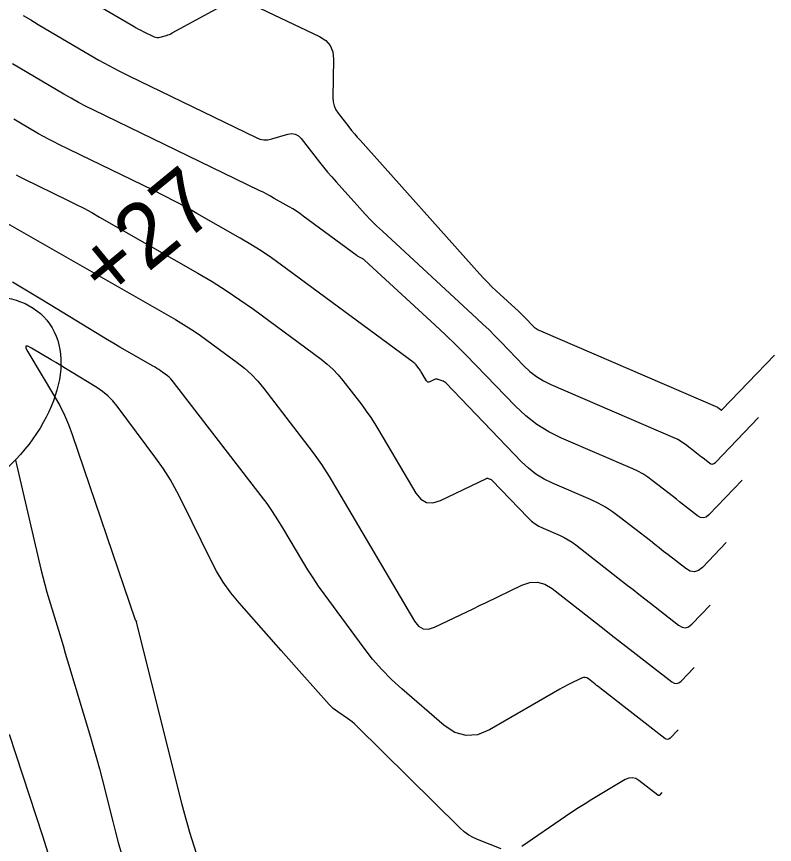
# Model space of a CAD drawing. Extents: x 1005228 to 1008882, y 1883389 to 1885754.
# Drawn here: x 1008264.2 to 1008338, y 1884272.3 to 1884352.9 of the extents above; entities that cross this region are included whole.
import ezdxf

# ---------------------------------------------------------------- set-up
doc = ezdxf.new("R2010")
doc.units = 0
for name, color, linetype in [('C-ANNO-NOTE', 7, 'Continuous'), ('R_Erosion', 7, 'Continuous'), ('S_BASELINE', 7, 'Continuous'), ('S_BRIDGE', 7, 'Continuous')]:
    doc.layers.add(name, color=color, linetype=linetype)

msp = doc.modelspace()

# ---------------------------------------------------------------- linework, layer by layer
at = {"layer": 'C-ANNO-NOTE'}
for points in [[(1008267.118, 1884356.928), (1008275.658, 1884351.886), (1008275.875, 1884351.761), (1008276.094, 1884351.641), (1008276.316, 1884351.525), (1008276.54, 1884351.413), (1008277.608, 1884350.895), (1008277.751, 1884350.84), (1008277.897, 1884350.813), (1008278.045, 1884350.815), (1008278.195, 1884350.844), (1008278.801, 1884351.019), (1008278.951, 1884351.067), (1008279.098, 1884351.122), (1008279.241, 1884351.186), (1008279.381, 1884351.258), (1008284.023, 1884353.818)], [(1008287.355, 1884353.92), (1008293.708, 1884350.909), (1008294.314, 1884350.526), (1008294.743, 1884350.033), (1008294.996, 1884349.43), (1008295.072, 1884348.718), (1008295.016, 1884344.963), (1008295.044, 1884344.55), (1008295.138, 1884344.16), (1008295.299, 1884343.793), (1008295.526, 1884343.448), (1008296.571, 1884342.113), (1008296.835, 1884341.782), (1008297.104, 1884341.455), (1008297.379, 1884341.132), (1008297.659, 1884340.814), (1008309.294, 1884327.798), (1008309.682, 1884327.374), (1008310.08, 1884326.96), (1008310.487, 1884326.556), (1008310.905, 1884326.162), (1008313.089, 1884324.148), (1008313.262, 1884323.986), (1008313.434, 1884323.821), (1008313.602, 1884323.653), (1008313.769, 1884323.483), (1008314.429, 1884322.797), (1008314.6, 1884322.635), (1008314.785, 1884322.493), (1008314.984, 1884322.37), (1008315.196, 1884322.266), (1008332.422, 1884314.831), (1008332.452, 1884314.817), (1008332.481, 1884314.801), (1008332.509, 1884314.783), (1008332.536, 1884314.764), (1008332.729, 1884314.613), (1008332.799, 1884314.558), (1008332.816, 1884314.549), (1008332.833, 1884314.546), (1008332.849, 1884314.551), (1008332.865, 1884314.563), (1008337.978, 1884319.903)], [(1008264.879, 1884352.959), (1008265.603, 1884352.524), (1008266.327, 1884352.092), (1008267.053, 1884351.662), (1008271.279, 1884349.168), (1008272.23, 1884348.619), (1008273.193, 1884348.09), (1008274.166, 1884347.581), (1008275.149, 1884347.091), (1008287.538, 1884341.078), (1008287.909, 1884340.936), (1008288.287, 1884340.866), (1008288.67, 1884340.87), (1008289.06, 1884340.947), (1008290.632, 1884341.399), (1008291.007, 1884341.458), (1008291.348, 1884341.408), (1008291.653, 1884341.249), (1008291.922, 1884340.982), (1008293.718, 1884338.688), (1008294.105, 1884338.202), (1008294.5, 1884337.722), (1008294.903, 1884337.249), (1008295.313, 1884336.782), (1008297.629, 1884334.191), (1008298.16, 1884333.611), (1008298.705, 1884333.045), (1008299.263, 1884332.492), (1008299.834, 1884331.952), (1008309.023, 1884323.481), (1008309.616, 1884322.925), (1008310.201, 1884322.362), (1008310.777, 1884321.789), (1008311.345, 1884321.208), (1008313.599, 1884318.865), (1008314.186, 1884318.313), (1008314.818, 1884317.826), (1008315.495, 1884317.405), (1008316.219, 1884317.05), (1008328.304, 1884311.835), (1008328.571, 1884311.709), (1008328.829, 1884311.567), (1008329.077, 1884311.409), (1008329.315, 1884311.235), (1008330.407, 1884310.382), (1008330.562, 1884310.261), (1008330.717, 1884310.14), (1008330.872, 1884310.019), (1008331.028, 1884309.897), (1008331.649, 1884309.412), (1008331.802, 1884309.324), (1008331.95, 1884309.302), (1008332.093, 1884309.345), (1008332.232, 1884309.454), (1008336.414, 1884313.822)], [(1008334.851, 1884307.742), (1008331.599, 1884304.346), (1008331.338, 1884304.139), (1008331.067, 1884304.057), (1008330.787, 1884304.1), (1008330.499, 1884304.266), (1008329.327, 1884305.182), (1008329.034, 1884305.41), (1008328.74, 1884305.639), (1008328.447, 1884305.868), (1008328.154, 1884306.097), (1008326.095, 1884307.706), (1008325.645, 1884308.035), (1008325.177, 1884308.333), (1008324.69, 1884308.601), (1008324.186, 1884308.838), (1008317.242, 1884311.835), (1008316.007, 1884312.441), (1008314.85, 1884313.159), (1008313.771, 1884313.99), (1008312.77, 1884314.934), (1008308.922, 1884318.932), (1008307.952, 1884319.925), (1008306.969, 1884320.902), (1008305.97, 1884321.865), (1008304.957, 1884322.813), (1008298.073, 1884329.16), (1008298.02, 1884329.205), (1008297.965, 1884329.245), (1008297.907, 1884329.282), (1008297.847, 1884329.314), (1008297.598, 1884329.436), (1008297.536, 1884329.468), (1008297.477, 1884329.503), (1008297.418, 1884329.54), (1008297.362, 1884329.58), (1008292.132, 1884333.435), (1008291.795, 1884333.676), (1008291.452, 1884333.906), (1008291.102, 1884334.127), (1008290.746, 1884334.338), (1008289.307, 1884335.16), (1008288.946, 1884335.362), (1008288.581, 1884335.559), (1008288.213, 1884335.749), (1008287.842, 1884335.933), (1008271.744, 1884343.746), (1008271.003, 1884344.115), (1008270.269, 1884344.499), (1008269.544, 1884344.898), (1008268.827, 1884345.312), (1008265.973, 1884346.996), (1008265.26, 1884347.418), (1008264.549, 1884347.843), (1008263.839, 1884348.269)], [(1008264.172, 1884337.456), (1008264.423, 1884337.318), (1008264.677, 1884337.184), (1008264.934, 1884337.057), (1008269.185, 1884334.993), (1008269.976, 1884334.601), (1008270.761, 1884334.196), (1008271.538, 1884333.777), (1008272.308, 1884333.345), (1008281.872, 1884327.879), (1008283.262, 1884327.058), (1008284.625, 1884326.198), (1008285.963, 1884325.299), (1008287.275, 1884324.361), (1008293.868, 1884319.501), (1008294.453, 1884319.038), (1008295, 1884318.538), (1008295.512, 1884318), (1008295.987, 1884317.426), (1008297.813, 1884315.053), (1008298.26, 1884314.453), (1008298.688, 1884313.841), (1008299.097, 1884313.215), (1008299.486, 1884312.577), (1008303.085, 1884306.469), (1008303.556, 1884305.877), (1008304.11, 1884305.56), (1008304.747, 1884305.515), (1008305.467, 1884305.744), (1008309.95, 1884307.894), (1008309.994, 1884307.911), (1008310.039, 1884307.918), (1008310.084, 1884307.915), (1008310.13, 1884307.903), (1008310.313, 1884307.837), (1008310.358, 1884307.818), (1008310.399, 1884307.794), (1008310.438, 1884307.766), (1008310.473, 1884307.733), (1008314.004, 1884304.064), (1008314.33, 1884303.757), (1008314.68, 1884303.487), (1008315.056, 1884303.253), (1008315.458, 1884303.056), (1008317.114, 1884302.342), (1008317.521, 1884302.151), (1008317.913, 1884301.935), (1008318.291, 1884301.694), (1008318.653, 1884301.429), (1008323.65, 1884297.526), (1008324.218, 1884297.082), (1008324.787, 1884296.638), (1008325.356, 1884296.194), (1008325.924, 1884295.75), (1008328.655, 1884293.618), (1008328.99, 1884293.424), (1008329.315, 1884293.375), (1008329.629, 1884293.47), (1008329.933, 1884293.71), (1008331.724, 1884295.581)], [(1008261.957, 1884333.497), (1008279.696, 1884323.358), (1008280.482, 1884322.894), (1008281.253, 1884322.408), (1008282.009, 1884321.899), (1008282.752, 1884321.368), (1008285.692, 1884319.201), (1008286.405, 1884318.636), (1008287.073, 1884318.026), (1008287.697, 1884317.37), (1008288.276, 1884316.67), (1008292.258, 1884311.496), (1008293.09, 1884310.38), (1008293.886, 1884309.241), (1008294.646, 1884308.077), (1008295.371, 1884306.889), (1008302.959, 1884294.013), (1008303.344, 1884293.528), (1008303.799, 1884293.268), (1008304.321, 1884293.231), (1008304.912, 1884293.419), (1008307.411, 1884294.617), (1008308.035, 1884294.917), (1008308.66, 1884295.218), (1008309.284, 1884295.518), (1008309.909, 1884295.819), (1008313.393, 1884297.5), (1008314.169, 1884297.766), (1008314.921, 1884297.802), (1008315.648, 1884297.607), (1008316.35, 1884297.183), (1008321.398, 1884293.241), (1008322.104, 1884292.689), (1008322.81, 1884292.137), (1008323.517, 1884291.586), (1008324.223, 1884291.034), (1008327.977, 1884288.103), (1008328.216, 1884287.965), (1008328.447, 1884287.931), (1008328.67, 1884287.998), (1008328.886, 1884288.169), (1008330.161, 1884289.5)], [(1008328.597, 1884283.419), (1008327.84, 1884282.628), (1008327.711, 1884282.526), (1008327.578, 1884282.486), (1008327.441, 1884282.507), (1008327.299, 1884282.589), (1008321.151, 1884287.389), (1008320.992, 1884287.513), (1008320.834, 1884287.637), (1008320.675, 1884287.76), (1008320.516, 1884287.884), (1008319.882, 1884288.38), (1008319.721, 1884288.477), (1008319.554, 1884288.522), (1008319.381, 1884288.514), (1008319.203, 1884288.453), (1008318.068, 1884287.905), (1008317.819, 1884287.782), (1008317.573, 1884287.655), (1008317.33, 1884287.523), (1008317.088, 1884287.387), (1008310.258, 1884283.442), (1008309.097, 1884282.957), (1008307.973, 1884282.865), (1008306.887, 1884283.166), (1008305.838, 1884283.86), (1008301.716, 1884287.422), (1008300.713, 1884288.338), (1008299.766, 1884289.306), (1008298.874, 1884290.325), (1008298.038, 1884291.396), (1008294.158, 1884296.66), (1008293.606, 1884297.429), (1008293.075, 1884298.211), (1008292.564, 1884299.007), (1008292.073, 1884299.816), (1008290.15, 1884303.079), (1008289.657, 1884303.887), (1008289.14, 1884304.678), (1008288.598, 1884305.453), (1008288.033, 1884306.212), (1008279.51, 1884317.286), (1008279.375, 1884317.448), (1008279.23, 1884317.6), (1008279.075, 1884317.742), (1008278.91, 1884317.873), (1008278.228, 1884318.376), (1008278.056, 1884318.499), (1008277.88, 1884318.617), (1008277.702, 1884318.73), (1008277.519, 1884318.837), (1008274.281, 1884320.688), (1008273.681, 1884321.034), (1008273.084, 1884321.384), (1008272.489, 1884321.739), (1008271.897, 1884322.098), (1008266.754, 1884325.242), (1008265.781, 1884325.836), (1008264.806, 1884326.427), (1008263.83, 1884327.016)], [(1008311.397, 1884271.855), (1008309.259, 1884272.679), (1008308.74, 1884272.91), (1008308.253, 1884273.189), (1008307.798, 1884273.518), (1008307.374, 1884273.896), (1008297.303, 1884283.836), (1008297.098, 1884284.029), (1008296.884, 1884284.212), (1008296.662, 1884284.384), (1008296.431, 1884284.546), (1008295.492, 1884285.172), (1008295.263, 1884285.335), (1008295.045, 1884285.512), (1008294.84, 1884285.703), (1008294.646, 1884285.906), (1008291.984, 1884288.889), (1008291.478, 1884289.456), (1008290.973, 1884290.025), (1008290.469, 1884290.594), (1008289.965, 1884291.164), (1008285.892, 1884295.783), (1008285.082, 1884296.767), (1008284.343, 1884297.799), (1008283.677, 1884298.879), (1008283.083, 1884300.006), (1008280.417, 1884305.507), (1008279.833, 1884306.644), (1008279.197, 1884307.75), (1008278.511, 1884308.826), (1008277.773, 1884309.87), (1008274.008, 1884314.942), (1008273.578, 1884315.467), (1008273.105, 1884315.944), (1008272.587, 1884316.373), (1008272.026, 1884316.754), (1008269.466, 1884318.319), (1008268.996, 1884318.606), (1008268.525, 1884318.892), (1008268.053, 1884319.176), (1008267.581, 1884319.46), (1008265.691, 1884320.591), (1008265.313, 1884320.78), (1008265.124, 1884320.78), (1008265.125, 1884320.591), (1008265.315, 1884320.214), (1008267.929, 1884315.879), (1008268.435, 1884314.988), (1008268.891, 1884314.073), (1008269.296, 1884313.136), (1008269.651, 1884312.175), (1008275.776, 1884294.14), (1008275.783, 1884294.124), (1008275.791, 1884294.11), (1008275.802, 1884294.097), (1008275.814, 1884294.086), (1008275.874, 1884294.039), (1008275.882, 1884294.03), (1008275.886, 1884294.021), (1008275.887, 1884294.011), (1008275.883, 1884293.999), (1008275.861, 1884293.952), (1008275.857, 1884293.94), (1008275.855, 1884293.928), (1008275.855, 1884293.916), (1008275.857, 1884293.903), (1008280.28, 1884276.278), (1008280.462, 1884275.574), (1008280.653, 1884274.873), (1008280.853, 1884274.175), (1008281.064, 1884273.479), (1008281.923, 1884270.701)], [(1008264.107, 1884309.663), (1008266.588, 1884299.083), (1008266.77, 1884298.33), (1008266.966, 1884297.581), (1008267.173, 1884296.835), (1008267.393, 1884296.092), (1008268.297, 1884293.128), (1008268.523, 1884292.387), (1008268.747, 1884291.645), (1008268.971, 1884290.903), (1008269.194, 1884290.161), (1008271.429, 1884282.704), (1008271.727, 1884281.688), (1008272.013, 1884280.669), (1008272.288, 1884279.646), (1008272.552, 1884278.621), (1008273.583, 1884274.512), (1008273.848, 1884273.487), (1008274.126, 1884272.466), (1008274.418, 1884271.449)], [(1008267.315, 1884271.432), (1008266.771, 1884273.092), (1008263.539, 1884282.961)], [(1008327.034, 1884277.339), (1008326.793, 1884277.087), (1008326.752, 1884277.054), (1008326.71, 1884277.042), (1008326.666, 1884277.048), (1008326.621, 1884277.074), (1008324.797, 1884278.498), (1008324.475, 1884278.69), (1008324.145, 1884278.768), (1008323.808, 1884278.732), (1008323.464, 1884278.581), (1008320.216, 1884276.64), (1008319.563, 1884276.243), (1008318.915, 1884275.835), (1008318.274, 1884275.417), (1008317.64, 1884274.99), (1008313.411, 1884272.091)]]:
    msp.add_lwpolyline(points, dxfattribs=at)
at = {"layer": 'R_Erosion'}
msp.add_ellipse((1008256.584, 1884314.613), major_axis=(10.591, 8.686), ratio=0.638788, dxfattribs=at)
at = {"layer": 'S_BRIDGE'}
msp.add_lwpolyline([(1008333.288, 1884301.661), (1008330.966, 1884299.237), (1008330.582, 1884298.934), (1008330.184, 1884298.813), (1008329.773, 1884298.875), (1008329.349, 1884299.12), (1008327.625, 1884300.466), (1008327.195, 1884300.802), (1008326.764, 1884301.139), (1008326.333, 1884301.475), (1008325.902, 1884301.811), (1008322.874, 1884304.177), (1008322.213, 1884304.66), (1008321.524, 1884305.099), (1008320.809, 1884305.493), (1008320.067, 1884305.841), (1008316.391, 1884307.428), (1008315.553, 1884307.839), (1008314.768, 1884308.327), (1008314.035, 1884308.891), (1008313.356, 1884309.531), (1008305.985, 1884317.191), (1008305.911, 1884317.259), (1008305.831, 1884317.318), (1008305.744, 1884317.368), (1008305.651, 1884317.407), (1008305.268, 1884317.546), (1008305.173, 1884317.571), (1008305.078, 1884317.576), (1008304.985, 1884317.561), (1008304.892, 1884317.527), (1008304.437, 1884317.309), (1008304.337, 1884317.277), (1008304.248, 1884317.283), (1008304.17, 1884317.327), (1008304.104, 1884317.41), (1008303.601, 1884318.264), (1008303.547, 1884318.353), (1008303.49, 1884318.441), (1008303.43, 1884318.526), (1008303.367, 1884318.61), (1008303.112, 1884318.942), (1008303.046, 1884319.022), (1008302.974, 1884319.097), (1008302.898, 1884319.167), (1008302.816, 1884319.232), (1008290.015, 1884328.668), (1008289.033, 1884329.37), (1008288.032, 1884330.043), (1008287.012, 1884330.686), (1008285.973, 1884331.3), (1008281.778, 1884333.698), (1008280.725, 1884334.288), (1008279.662, 1884334.86), (1008278.59, 1884335.415), (1008277.508, 1884335.951), (1008268.339, 1884340.401), (1008267.84, 1884340.65), (1008267.346, 1884340.908), (1008266.858, 1884341.177), (1008266.375, 1884341.456), (1008264.453, 1884342.59), (1008263.973, 1884342.874)], dxfattribs=at)

# ---------------------------------------------------------------- texts
at = {"layer": 'S_BASELINE'}
msp.add_text('+27', height=6.2498, rotation=39.35432, dxfattribs=at).set_placement((1008273.21, 1884324.802))

doc.saveas('drawing.dxf')
